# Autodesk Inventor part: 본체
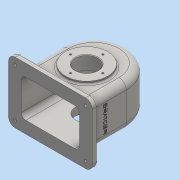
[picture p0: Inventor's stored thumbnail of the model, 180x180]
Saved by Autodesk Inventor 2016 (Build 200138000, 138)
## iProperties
Created: 2018-11
Part Number: 본체
Material: 일반
Document SubType Name: Modeling
Designer: 공506_40
Density: 1 g/cm^3
Appearance: 기본값
Author: 공506_40
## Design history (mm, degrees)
sketch "스케치3"
  geometry: L1 (-75, 55)-(75, 55); L2 (75, 55)-(75, -55); L3 (75, -55)-(-75, -55); L4 (-75, -55)-(-75, 55); L5 (-75, 55)-(75, -55); L6 (75, 55)-(-75, -55); 1 further point
  constraints: 12 end point, 2 midpoint, 2 parallel, 1 horizontal, 1 perpendicular
  dimensions: "d4" = 150 distance of L2.end L3.end; "d5" = 110 distance of L3.end L1.start
extrude "돌출1" new body sketch "스케치3" distance "d6" = 10; taper "d7" = 0 deg
sketch "스케치4"
  geometry: L1 (58, -38.5)-(-58, -38.5); L2 (-58, -38.5)-(-58, 38.5); L3 (-58, 38.5)-(58, 38.5); L4 (58, 38.5)-(58, -38.5); L5 (58, -38.5)-(-58, 38.5); L6 (-58, -38.5)-(58, 38.5); 1 further point
  constraints: 12 end point, 2 midpoint, 2 parallel, 1 horizontal, 1 perpendicular
  dimensions: "d8" = 77 distance of L1.end L2.end; "d9" = 116 distance of L2.end L3.end
extrude "돌출2" join sketch "스케치4" distance "d10" = 126; taper "d11" = 0 deg
fillet "모깎기1" dims "d12" = 58
fillet "모깎기2" dims "d13" = 12
fillet "모깎기3" dims "d14" = 3
sketch "스케치5"
  geometry: L1 (-75, -43)-(-75, 43) reference; L2 (-63, 55)-(63, 55) reference; L3 (75, 43)-(75, -43) reference; L4 (63, -55)-(-63, -55) reference; A1 r 12 centre (-63, -43) between (-75, -43) and (-63, -55) reference; A2 r 12 centre (-63, 43) between (-63, 55) and (-75, 43) reference; A3 r 12 centre (63, 43) between (75, 43) and (63, 55) reference; A4 r 12 centre (63, -43) between (63, -55) and (75, -43) reference; 5 further points
  constraints: 4 coincident
hole "구멍1" sketch "스케치5" at (-63, -43), (-63, 43), (63, 43), (63, -43) diameter "d15" = 5; stored, may be unused: countersink angle "d19" = 90 deg, drill point angle "d21" = 118 deg; dims "d16" = 6, "d17" = 12, "d18" = 4, "d20" = 10
sketch "스케치9"
  geometry: L1 (58, 0)-(58, 68) reference; L2 (-58, 0)-(-58, 68) reference; L3 (63, -10)-(-63, -10) reference; L4 (-52, -10)-(-52, 68); L5 (52, 68)-(52, -10); L6 (52, -10)-(-52, -10); A1 r 58 centre (0, 68) between (58, 68) and (-58, 68) reference; A2 r 52 centre (0, 68) between (52, 68) and (-52, 68); 1 further point
  constraints: 6 end point, 2 point on circle, 2 point on line, 2 tangent, 2 vertical, 1 centre point, 1 collinear
  dimensions: "d27" = 6 radial gap between concentric circles of A1 A2
extrude "돌출3" cut sketch "스케치9" stored distance "d28" = 67; taper "d29" = 0 deg
sketch "스케치10"
  geometry: L1 (0, 0)-(0, 68) reference; C1 r 38 at (58, 55); 1 further point
  constraints: 1 centre point
  dimensions: "d30" = 55 distance of point (58, 0) C1.centre; "d31" = 58 distance from line of L1 C1.centre; "d32" = 76 diameter of C1
extrude "돌출4" join sketch "스케치10" distance "d33" = 5; taper "d34" = 0 deg
node "작업 평면1"
sketch "스케치12"
  geometry: C1 r 38 at (0, 55) reference; C2 r 28 at (0, 55); 1 further point
  constraints: 1 centre point, 1 coincident
  dimensions: "d36" = 56 diameter of C2
extrude "돌출5" join sketch "스케치12" stored distance "d37" = 5; taper "d38" = 40 deg
sketch "스케치13"
  geometry: L1 (0, 0)-(0, 68) reference; L2 (121, 0)-(-5, 0) reference; C1 r 38 at (58, 55); 1 further point
  constraints: 1 centre point
  dimensions: "d39" = 76 diameter of C1; "d40" = 58 distance from line of L1 C1.centre; "d41" = 55 distance from line of L2 C1.centre
extrude "돌출6" join sketch "스케치13" distance "d42" = 10; taper "d43" = 0 deg
sketch "스케치14"
  geometry: C1 r 38 at (0, 0) reference; C2 r 20 at (0, 0); 1 further point
  constraints: 1 centre point, 1 coincident
  dimensions: "d44" = 40 diameter of C2
extrude "돌출7" cut sketch "스케치14" distance "d45" = 247.25; taper "d46" = 0 deg
fillet "모깎기4" dims "d47" = 8
fillet "모깎기5" dims "d48" = 13
fillet "모깎기6" dims "d49" = 3
fillet "모깎기7" dims "d50" = 3
node "작업 평면2"
sketch "스케치15"
  geometry: C1 r 6 at (0, 0); 1 further point
  constraints: 1 centre point, 1 coincident
  dimensions: "d52" = 12 diameter of C1
extrude "돌출8" join sketch "스케치15" stored distance "d53" = 247.25; taper "d54" = 5 deg
fillet "모깎기8" dims "d55" = 3
sketch "스케치16"
  geometry: C1 r 20 at (0, 0) reference; 2 further points
  constraints: 1 vertical alignment
  dimensions: "d56" = 29 distance of C1.centre point (0, 29)
hole "구멍2" sketch "스케치16" at (0, 29) diameter "d57" = 3.242; stored, may be unused: countersink angle "d61" = 90 deg, drill point angle "d63" = 118 deg; dims "d58" = 8, "d59" = 12, "d60" = 4, "d62" = 10
sketch "스케치17"
  geometry: C1 r 20 at (0, 0) reference; 2 further points
  constraints: 1 horizontal alignment
  dimensions: "d67" = 29 distance of C1.centre point (29, 0)
hole "구멍3" sketch "스케치17" at (29, 0) diameter "d68" = 3.242; stored, may be unused: countersink angle "d72" = 90 deg, drill point angle "d74" = 118 deg; dims "d69" = 8, "d70" = 12, "d71" = 4, "d73" = 10
sketch "스케치18"
  geometry: 2 further points
  constraints: 1 coincident
hole "구멍4" sketch "스케치18" at (0, 0) diameter "d78" = 4.134; stored, may be unused: countersink angle "d82" = 90 deg, drill point angle "d84" = 118 deg; dims "d79" = 20, "d80" = 12, "d81" = 4, "d83" = 20
chamfer "모따기1" distance "d85" = 1; stored, may be unused: second distance "d86" = 2, angle "d87" = 45 deg
chamfer "모따기2" distance "d88" = 1; stored, may be unused: second distance "d89" = 2, angle "d90" = 45 deg
sketch "스케치19"
  geometry: L1 (68.5, -78)-(-17.5, -78) reference; L2 (-13, 0)-(-13, -65) reference; 2 further points
  constraints: 1 other
  dimensions: "d91" = 40 distance from line of L1 point (25.5, -38); "d92" = 38.5 distance from line of point (25.5, -38) L2
feature "엠보싱1" sketch "스케치19" dims "d4" = 150, "d5" = 110, "d93" = 0.5, "d94" = 0
node "솔리드1"
pattern_circular "원형 패턴1" dims angle "d65" = 360 deg
pattern_circular "원형 패턴2" dims angle "d76" = 360 deg
node "투영된 루프1"
node "투영된 루프3"
node "투영된 루프4"
other parameters: "d35" = 14, "d51" = 132
